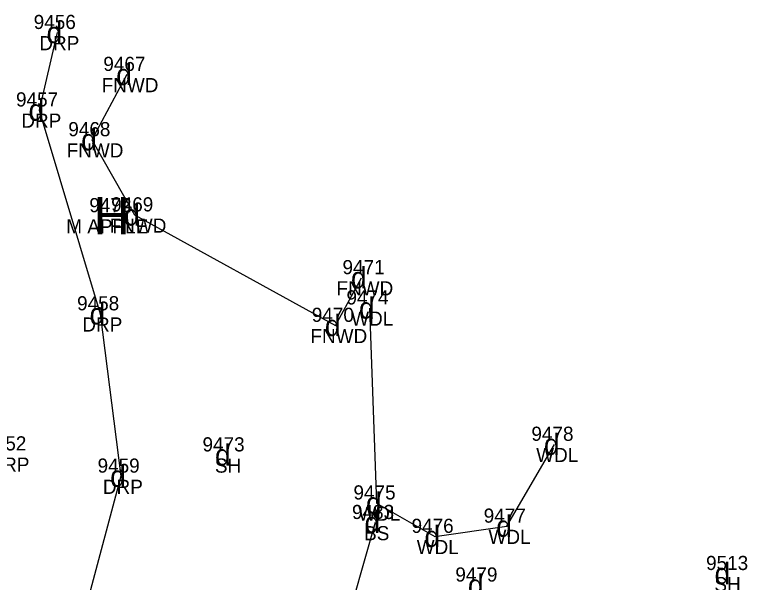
# Model space of a CAD drawing. Extents: x 69415 to 80913, y 7576 to 15059.
# Drawn here: x 78522.5 to 78626.1, y 12705.2 to 12785.4 of the extents above; entities that cross this region are included whole.
import ezdxf

# ---------------------------------------------------------------- set-up
doc = ezdxf.new("R2010")
doc.units = 0
for name, color, linetype in [('Level 11', 7, 'Continuous'), ('Level 12', 7, 'Continuous'), ('Level 14', 7, 'Continuous'), ('Level 46', 7, 'Continuous'), ('Level 47', 7, 'Continuous'), ('Level 48', 7, 'Continuous')]:
    doc.layers.add(name, color=color, linetype=linetype)

msp = doc.modelspace()

# ---------------------------------------------------------------- linework, layer by layer
at = {"layer": 'Level 11'}
for p, q in [((78528.52, 12782.91), (78525.97, 12771.96)), ((78525.97, 12771.96), (78534.6, 12743.15)), ((78534.6, 12743.15), (78537.51, 12720.21)), ((78537.51, 12720.21), (78532.6, 12701.8))]:
    msp.add_line(p, q, dxfattribs=at)
at = {"layer": 'Level 12'}
for p, q in [((78538.36, 12776.98), (78533.41, 12767.76)), ((78533.41, 12767.76), (78539.48, 12757.13)), ((78539.48, 12757.13), (78567.86, 12741.52)), ((78567.86, 12741.52), (78571.55, 12748.26))]:
    msp.add_line(p, q, dxfattribs=at)
at = {"layer": 'Level 14'}
for p, q in [((78572.68, 12743.98), (78573.67, 12716.42)), ((78592.08, 12713.14), (78598.82, 12724.71)), ((78573.67, 12716.42), (78581.93, 12711.7)), ((78581.93, 12711.7), (78592.08, 12713.14))]:
    msp.add_line(p, q, dxfattribs=at)
at = {"layer": 'Level 48'}
msp.add_line((78573.46, 12713.66), (78565.52, 12685.88), dxfattribs=at)

# ---------------------------------------------------------------- texts
at = {"layer": 'Level 14'}
msp.add_text('H', height=5.3, dxfattribs=at).set_placement((78533.68, 12754.37))
at = {"layer": 'Level 46'}
for s, p in [('9456', (78525.21, 12783.41)), ('DRP', (78526.01, 12780.41)), ('9467', (78535.05, 12777.48)), ('FNWD', (78534.82, 12774.48)), ('9457', (78522.71, 12772.46)), ('DRP', (78523.46, 12769.46)), ('9468', (78530.1, 12768.26)), ('FNWD', (78529.87, 12765.26)), ('9472', (78533.07, 12757.52)), ('9469', (78536.16, 12757.63)), ('M APPLE', (78529.81, 12754.52)), ('FNWD', (78535.94, 12754.63)), ('9471', (78568.86, 12748.76)), ('FNWD', (78568.01, 12745.76)), ('9474', (78569.42, 12744.48)), ('9458', (78531.34, 12743.65)), ('9470', (78564.52, 12742.02)), ('WDL', (78570.09, 12741.48)), ('DRP', (78532.09, 12740.65)), ('FNWD', (78564.33, 12739.02)), ('9478', (78595.56, 12725.21)), ('9452', (78518.22, 12723.85)), ('9473', (78549.07, 12723.71)), ('WDL', (78596.24, 12722.21)), ('DRP', (78518.96, 12720.85)), ('9459', (78534.24, 12720.71)), ('SH', (78550.82, 12720.71)), ('DRP', (78534.99, 12717.71)), ('9475', (78570.41, 12716.92)), ('9483', (78570.2, 12714.16)), ('WDL', (78571.09, 12713.92)), ('9477', (78588.82, 12713.64)), ('9476', (78578.62, 12712.2)), ('BS', (78571.91, 12711.16)), ('WDL', (78589.5, 12710.64)), ('WDL', (78579.35, 12709.2)), ('9513', (78620.25, 12706.95)), ('9479', (78584.81, 12705.32)), ('SH', (78621.43, 12703.95))]:
    msp.add_text(s, height=2, dxfattribs=at).set_placement(p)
at = {"layer": 'Level 47'}
for p in [(78527.02, 12781.41), (78536.86, 12775.48), (78524.47, 12770.46), (78531.91, 12766.26), (78537.98, 12755.63), (78570.05, 12746.76), (78571.18, 12742.48), (78533.1, 12741.65), (78566.36, 12740.02), (78597.32, 12723.21), (78550.83, 12721.71), (78536.01, 12718.71), (78572.17, 12714.92), (78571.96, 12712.16), (78590.58, 12711.64), (78580.43, 12710.2), (78621.44, 12704.95), (78586.58, 12703.32)]:
    msp.add_text('d', height=3, dxfattribs=at).set_placement(p)

doc.saveas('drawing.dxf')
